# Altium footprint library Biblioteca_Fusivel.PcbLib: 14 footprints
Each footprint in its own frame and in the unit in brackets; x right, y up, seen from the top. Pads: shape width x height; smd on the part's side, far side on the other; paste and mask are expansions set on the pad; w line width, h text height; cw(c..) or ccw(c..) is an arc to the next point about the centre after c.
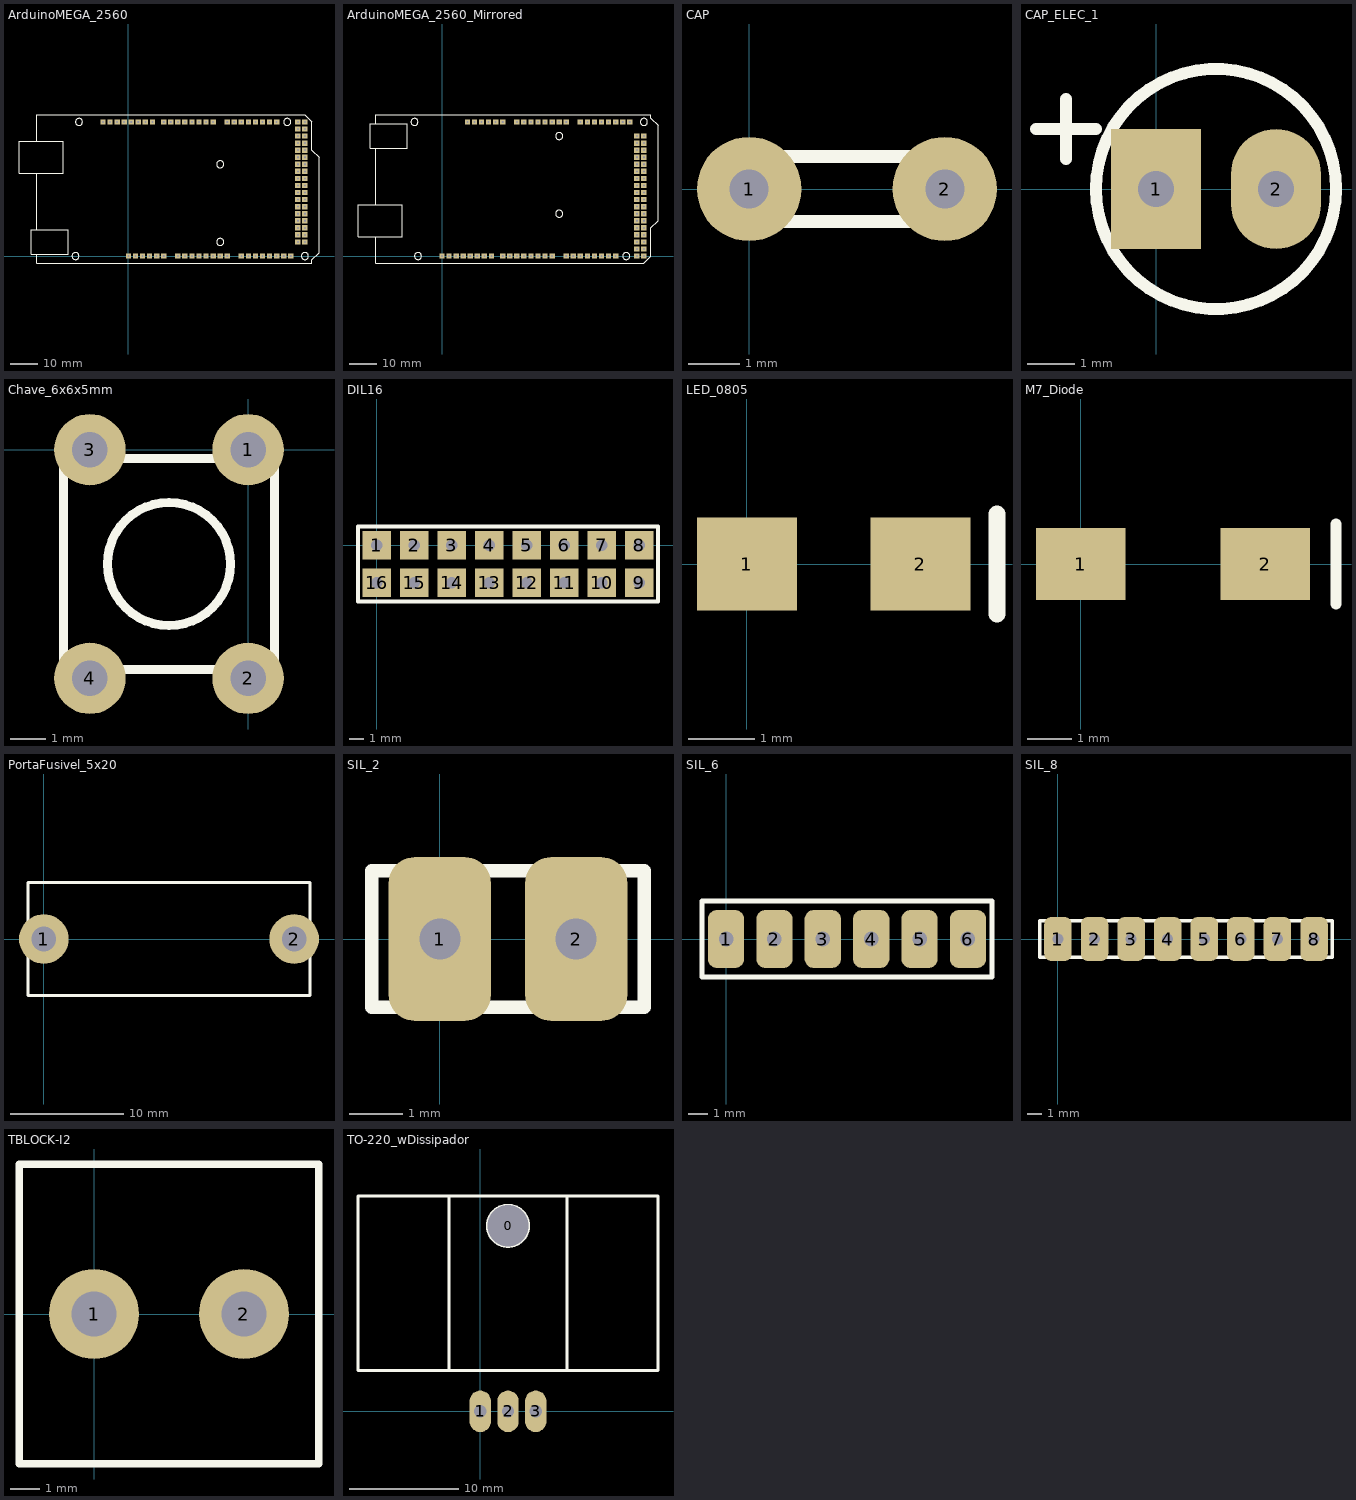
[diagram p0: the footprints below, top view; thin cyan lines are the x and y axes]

## ArduinoMEGA_2560 [mil] "ArduinoMEGA_2560"
pads (82):
  rect 75x75 hole 30: 0(1200,1900) 1(1100,1900) 2(1000,1900) 3(900,1900) 3V3(100,0) 4(800,1900) 5(700,1900) 5V(200,0) 5V(2400,1900) 5V(2500,1900) 6(600,1900) 7(500,1900) 8(340,1900) 9(240,1900) 10(140,1900) 11(40,1900) 12(-60,1900) 13(-160,1900) 14(1400,1900) 15(1500,1900) 16(1600,1900) 17(1700,1900) 18(1800,1900) 19(1900,1900) 20(2000,1900) 21(2100,1900) 22(2400,1800) 23(2500,1800) 24(2400,1700) 25(2500,1700) 26(2400,1600) 27(2500,1600) 28(2400,1500) 29(2500,1500) 30(2400,1400) 31(2500,1400) 32(2400,1300) 33(2500,1300) 34(2400,1200) 35(2500,1200) 36(2400,1100) 37(2500,1100) 38(2400,1000) 39(2500,1000) 40(2400,900) 41(2500,900) 42(2400,800) 43(2500,800) 44(2400,700) 45(2500,700) 46(2400,600) 47(2500,600) 48(2400,500) 49(2500,500) 50(2400,400) 51(2500,400) 52(2400,300) 53(2500,300) A0(700,0) A1(800,0) A2(900,0) A3(1000,0) A4(1100,0) A5(1200,0) A6(1300,0) A7(1400,0) A8(1600,0) A9(1700,0) A10(1800,0) A11(1900,0) A12(2000,0) A13(2100,0) A14(2200,0) A15(2300,0) AREF(-360,1900) GND(-260,1900) GND(300,0) GND(400,0) GND(2400,200) GND(2500,200) RESET(0,0) Vin(500,0)
Top Overlay:
  circle w10: c1300,1300 r50
  circle w10: c1300,200 r50
  circle w10: c-750,0 r50
  circle w10: c-700,1900 r50
  circle w10: c2500,0 r50
  circle w10: c2250,1900 r50
  lines w10: -1300,25 -1300,-100 2600,-100 2600,-50 2700,50 2700,1400 2600,1500 2600,1900 2500,2000 -1300,2000 -1300,1625 ; -1300,375 -1300,1175 ; -1550,1175 -925,1175 -925,1625 -1550,1625 -1550,1175 ; -1375,25 -850,25 -850,375 -1375,375 -1375,25

## ArduinoMEGA_2560_Mirrored [mil] "Arduino MEGA 2560 Espelhado"
pads (82):
  rect 75x75 hole 30: 0(1560,0) 1(1460,0) 2(1360,0) 3(1260,0) 3V3(460,1900) 4(1160,0) 5(1060,0) 5V(560,1900) 5V(2760,0) 5V(2860,0) 6(960,0) 7(860,0) 8(700,0) 9(600,0) 10(500,0) 11(400,0) 12(300,0) 13(200,0) 14(1760,0) 15(1860,0) 16(1960,0) 17(2060,0) 18(2160,0) 19(2260,0) 20(2360,0) 21(2460,0) 22(2760,100) 23(2860,100) 24(2760,200) 25(2860,200) 26(2760,300) 27(2860,300) 28(2760,400) 29(2860,400) 30(2760,500) 31(2860,500) 32(2760,600) 33(2860,600) 34(2760,700) 35(2860,700) 36(2760,800) 37(2860,800) 38(2760,900) 39(2860,900) 40(2760,1000) 41(2860,1000) 42(2760,1100) 43(2860,1100) 44(2760,1200) 45(2860,1200) 46(2760,1300) 47(2860,1300) 48(2760,1400) 49(2860,1400) 50(2760,1500) 51(2860,1500) 52(2760,1600) 53(2860,1600) A0(1060,1900) A1(1160,1900) A2(1260,1900) A3(1360,1900) A4(1460,1900) A5(1560,1900) A6(1660,1900) A7(1760,1900) A8(1960,1900) A9(2060,1900) A10(2160,1900) A11(2260,1900) A12(2360,1900) A13(2460,1900) A14(2560,1900) A15(2660,1900) AREF(0,0) GND(100,0) GND(660,1900) GND(760,1900) GND(2760,1700) GND(2860,1700) RESET(360,1900) Vin(860,1900)
Top Overlay:
  circle w10: c2610,0 r50
  circle w10: c-390,1900 r50
  circle w10: c1660,600 r50
  circle w10: c1660,1700 r50
  circle w10: c2860,1900 r50
  circle w10: c-340,0 r50
  lines w10: -940,275 -940,-100 2860,-100 2960,0 2960,400 3060,500 3060,1850 2960,1950 2960,2000 -940,2000 -940,1875 ; -940,725 -940,1525 ; -1190,275 -1190,725 -565,725 -565,275 -1190,275 ; -1015,1525 -1015,1875 -490,1875 -490,1525 -1015,1525

## CAP [mil] "CAP"
pads (2):
  round 80 hole 30: 1(0,0) 2(150,0)
Top Overlay:
  lines w10: 0,-25 0,25 150,25 150,-25 0,-25

## CAP_ELEC_1 [mil] "CAP_ELEC_1"
pads (2):
  rect 75x100 hole 30: 1(0,0)
  oval 75x100 hole 30: 2(100,0)
Top Overlay:
  circle w10: c50,0 r100
  lines w10: -100,50 -50,50 ; -75,25 -75,75

## Chave_6x6x5mm [mil] "Chave_6x6x5mm"
pads (4):
  round 80 hole 40: 1(0,0) 2(0,-255.91) 3(-177.17,0) 4(-177.17,-255.91)
Top Overlay:
  circle w10: c-88.58,-127.95 r68.9
  lines w10: -206.69,-246.06 29.53,-246.06 29.53,-9.84 -206.69,-9.84 -206.69,-246.06

## DIL16 [mil] "DIL16"
pads (16):
  rect 75x75 hole 30: 1(0,0) 2(100,0) 3(200,0) 4(300,0) 5(400,0) 6(500,0) 7(600,0) 8(700,0) 9(700,-100) 10(600,-100) 11(500,-100) 12(400,-100) 13(300,-100) 14(200,-100) 15(100,-100) 16(0,-100)
Top Overlay:
  lines w10: -50,-150 750,-150 750,50 -50,50 -50,-150

## LED_0805 [mm] "LED_0805"
pads (2):
  rect 1.5x1.4 smd: 1(0,0) 2(2.6,0)
Top Overlay:
  lines w0.254: 3.75,-0.75 3.75,0.75

## M7_Diode [mm] "M7_Diode"
pads (2):
  rect 2x1.6 smd: 1(0,0) 2(4.11,0)
Top Overlay:
  lines w0.254: 5.69,-0.889 5.69,0.889

## PortaFusivel_5x20 [mm] "PortaFusivel_5x20"
pads (2):
  round 4.4 hole 2.2: 1(0,0) 2(22.2,0)
Top Overlay:
  lines w0.254: -1.4,-5 -1.4,5 23.6,5 23.6,-5 -1.4,-5

## SIL_2 [mil] "SIL_2"
pads (2):
  rrect50% 75x120 hole 30: 1(0,0) 2(100,0)
Top Overlay:
  lines w10: -50,-50 -50,50 150,50 150,-50 -50,-50

## SIL_6 [mil] "SIL_6"
pads (6):
  rrect50% 75x120 hole 30: 1(0,0) 2(100,0) 3(200,0) 4(300,0) 5(400,0) 6(500,0)
Top Overlay:
  lines w10: -50,-78.74 -50,78.74 550,78.74 550,-78.74 -50,-78.74

## SIL_8 [mil] "SIL_8"
pads (8):
  rrect50% 75x120 hole 30: 1(0,0) 2(100,0) 3(200,0) 4(300,0) 5(400,0) 6(500,0) 7(600,0) 8(700,0)
Top Overlay:
  lines w10: -50,-50 750,-50 750,50 -50,50 -50,-50

## TBLOCK-I2 [mil] "Borne KRE - 2 Vias"
pads (2):
  round 120 hole 60: 1(0,0) 2(200,0)
Top Overlay:
  lines w10: -100,-200 300,-200 300,200 -100,200 -100,0 -100,-200

## TO-220_wDissipador [mil] "TO-220_wDissipador"
pads (4):
  round 60 hole 149.61: 0(100,669.29)
  oval 77x150 hole 45: 1(0,0) 2(100,0) 3(200,0)
Top Overlay:
  circle w10: c100,669.29 r74.8
  lines w10: -112.6,147.64 -112.6,777.56 ; 312.6,147.64 312.6,777.56 ; -441.34,147.64 641.34,147.64 641.34,777.56 -441.34,777.56 -441.34,147.64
